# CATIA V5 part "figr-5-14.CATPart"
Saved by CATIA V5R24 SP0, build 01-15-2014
Part number: Part1
Bounding box of the stored display mesh (mm): x 0 to 150, y -70 to 70, z -150 to 69.804
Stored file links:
  D:\KAVITA\CATIA V5-6R2014 Project_ Kavita\CATIA V5-6R2014_partfiles\Partfiles\c05_catia_v5-6r2014_prt\figr-5-14.CATPart
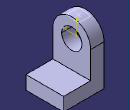
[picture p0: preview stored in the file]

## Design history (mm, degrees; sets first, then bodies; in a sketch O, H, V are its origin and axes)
Set1
  Plane1: type Offset, RefPlane face of Pad1, Offset -18, reversed
  Plane2: type Tangent, Support face of Pad1, RefPoint Sketch3
Body1 (main body)
  Sketch1 on yz-plane, origin (0, 0, 0), H (0, 1, 0), V (0, 0, 1)
    arc A1 centre (0, 0) radius 70 from (70, 0) to (-70, 0) ccw
    point P1 (70, 0)
    point P2 (-70, 0)
    line L1 (-70, 0) -> (-70, -150)
    line L2 (-70, -150) -> (70, -150)
    line L3 (70, -150) -> (70, 0)
    circle A2 centre (0, 0) radius 37.5
    radius A1 = 70
    radius A2 = 37.5
    distance O L2 = 150
    coincidence: P1 H, P2 H
    tangency: L1 A1, L3 A1
    horizontal: L2 H
  Pad1: profile Sketch1, direction (1, 0, 0), length 50
  Sketch2 on face of Pad1, origin (50, 0, 0), H (0, 1, 0), V (0, 0, 1)
    line L1 (-70, -150) -> (70, -150)
    line L2 (70, -150) -> (70, -100)
    line L3 (70, -100) -> (-70, -100)
    line L4 (-70, -100) -> (-70, -150)
    reference projected line E1 (-70, -150) -> (70, -150) from edge [face of Pad1 | face of Pad1]
    reference projected line E2 (-70, 0) -> (-70, -150) from edge [face of Pad1 | face of Pad1]
    reference projected line E3 (70, -150) -> (70, 0) from edge [face of Pad1 | face of Pad1]
    length L2 = 50
    horizontal: L1 H, L3 H
    vertical: L2 V, L4 V
    coincidence: L1 E1, E2 L4, L2 E3
  Pad2: profile Sketch2, direction (1, 0, 0), length 100
  Sketch3 on Plane1, origin (32, 0, 0), H (0, -1, 0), V (0, 0, 1)
    point P1 (-7.2142, 69.6273)
    reference projected arc E1 centre (0, 0) radius 70 from (70, 0) to (-70, 0) ccw from edge [face of Pad1 | face of Pad1]
    coincidence: P1 E1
